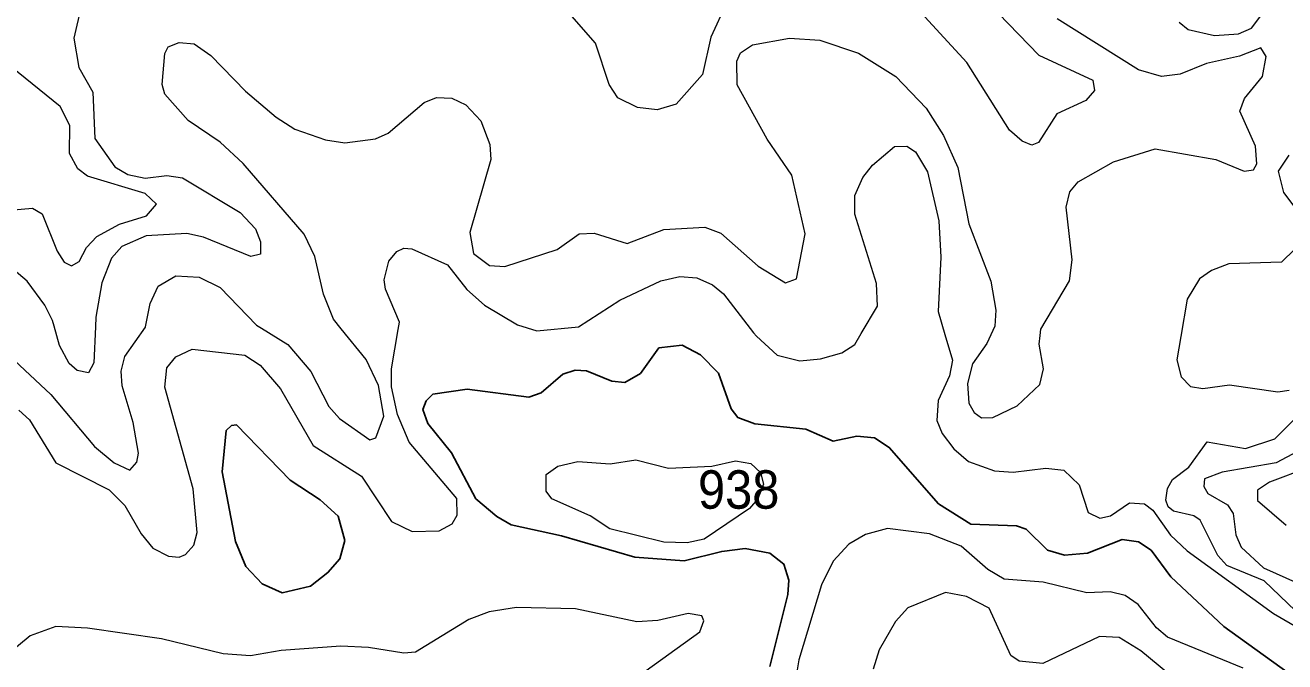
# Model space of a CAD drawing. Extents: x 473.9 to 500, y 7733.1 to 7760.8.
# Drawn here: x 484.875 to 487.498, y 7757.279 to 7758.604 of the extents above; entities that cross this region are included whole.
import ezdxf

# ---------------------------------------------------------------- set-up
doc = ezdxf.new("R2010")
doc.units = 0
doc.header["$LTSCALE"] = 0.032
doc.layers.add('1', color=7, linetype='Continuous', lineweight=25)
doc.layers.add('2', color=7, linetype='Continuous', lineweight=13)
doc.layers.add('21', color=7, linetype='Continuous')

msp = doc.modelspace()

# ---------------------------------------------------------------- linework, layer by layer
at = {"layer": '1'}
for points in [[(486.0435, 7757.8843), (486.0967, 7757.8628), (486.1233, 7757.8604), (486.1561, 7757.8791), (486.1947, 7757.9324), (486.2429, 7757.9381), (486.281, 7757.9181), (486.3185, 7757.8799), (486.3448, 7757.8054), (486.3589, 7757.7872), (486.3945, 7757.7739), (486.5005, 7757.7633), (486.5577, 7757.7384), (486.607, 7757.7485), (486.6436, 7757.7453), (486.6745, 7757.7251), (486.7769, 7757.6077), (486.8447, 7757.565), (486.9396, 7757.5622), (486.9595, 7757.5546), (487.0042, 7757.5114), (487.0392, 7757.5011), (487.0877, 7757.5051), (487.1598, 7757.5335), (487.1933, 7757.5289), (487.22, 7757.5109), (487.2612, 7757.4555), (487.3716, 7757.3522), (487.5572, 7757.2184)], [(486.4257, 7757.269), (486.4634, 7757.4186), (486.4652, 7757.4491), (486.4549, 7757.4823), (486.426, 7757.5052), (486.3745, 7757.5144), (486.3254, 7757.5086), (486.2471, 7757.4888), (486.1444, 7757.4963), (485.992, 7757.5411), (485.8872, 7757.5637), (485.8569, 7757.5812), (485.8136, 7757.6184), (485.7625, 7757.7136), (485.713, 7757.7747), (485.7027, 7757.8037), (485.71, 7757.8223), (485.724, 7757.8357), (485.7955, 7757.8466), (485.9239, 7757.8298), (485.9496, 7757.8387), (485.9948, 7757.8777), (486.0204, 7757.8859), (486.0435, 7757.8843)]]:
    msp.add_lwpolyline(points, dxfattribs=at)
msp.add_lwpolyline([(485.4893, 7757.6158), (485.4266, 7757.657), (485.3147, 7757.7719), (485.3044, 7757.771), (485.2935, 7757.76), (485.2846, 7757.674), (485.3128, 7757.5292), (485.334, 7757.4774), (485.3681, 7757.4408), (485.4095, 7757.4226), (485.4688, 7757.4365), (485.5051, 7757.4644), (485.53, 7757.4932), (485.5402, 7757.5314), (485.5266, 7757.5818)], close=True, dxfattribs=at)
at = {"layer": '2'}
for points in [[(487.2783, 7758.6104), (487.2968, 7758.595), (487.3521, 7758.5827), (487.4018, 7758.586), (487.4292, 7758.5981), (487.4871, 7758.6753)], [(486.3356, 7758.6496), (486.3029, 7758.5793), (486.2855, 7758.5012), (486.2308, 7758.4399), (486.1909, 7758.428), (486.1497, 7758.4328), (486.1091, 7758.4529), (486.0912, 7758.4802), (486.0622, 7758.5665), (485.9987, 7758.6397)], [(486.9018, 7758.6285), (486.9859, 7758.5414), (487.0987, 7758.4896), (487.1019, 7758.4683), (487.0839, 7758.4474), (487.0232, 7758.4195), (486.9856, 7758.3598), (486.9711, 7758.3541), (486.9511, 7758.3626), (486.9249, 7758.3853), (486.8363, 7758.5261), (486.7166, 7758.6562)], [(484.9914, 7758.6432), (484.9758, 7758.5773), (484.9861, 7758.5162), (485.0157, 7758.4647), (485.0193, 7758.3678), (485.0612, 7758.3089), (485.0882, 7758.2934), (485.1242, 7758.2858), (485.1698, 7758.2913), (485.2019, 7758.2865), (485.3227, 7758.2144), (485.354, 7758.18), (485.3647, 7758.1527), (485.3647, 7758.1273), (485.3444, 7758.1224), (485.2461, 7758.1628), (485.2116, 7758.1706), (485.1264, 7758.1656), (485.0758, 7758.1432), (485.0546, 7758.1192), (485.0344, 7758.068), (485.0217, 7757.9962), (485.0208, 7757.9764), (485.0176, 7757.9013), (485.0062, 7757.8806), (484.9825, 7757.885), (484.9662, 7757.8997), (484.9458, 7757.9374), (484.935, 7757.9772), (484.9317, 7757.9892), (484.9157, 7758.0215), (484.8785, 7758.071), (484.8383, 7758.1053)], [(486.1285, 7758.1499), (486.2048, 7758.1785), (486.2906, 7758.1835), (486.3238, 7758.171), (486.4017, 7758.1027), (486.4585, 7758.0679), (486.4811, 7758.0762), (486.4994, 7758.1698), (486.4712, 7758.2917), (486.4204, 7758.3665), (486.3579, 7758.48), (486.357, 7758.5293), (486.3647, 7758.5464), (486.3896, 7758.563), (486.4664, 7758.5767), (486.5298, 7758.5729), (486.6103, 7758.5456), (486.6879, 7758.4975), (486.7514, 7758.4315), (486.7872, 7758.3742), (486.8174, 7758.3075), (486.8405, 7758.1903), (486.8859, 7758.071), (486.8965, 7758.0106), (486.8941, 7757.9772), (486.8859, 7757.9594), (486.8777, 7757.9416), (486.8478, 7757.8994), (486.8376, 7757.8581), (486.8399, 7757.8175), (486.8513, 7757.7975), (486.8664, 7757.7865), (486.8901, 7757.7876), (486.9408, 7757.8115), (486.9882, 7757.8563), (486.996, 7757.8884), (486.9867, 7757.9399), (486.9887, 7757.9584), (486.99, 7757.9709), (487.0502, 7758.0722), (487.0557, 7758.1156), (487.043, 7758.2251), (487.0504, 7758.2572), (487.0683, 7758.278), (487.1415, 7758.3199), (487.2286, 7758.3467), (487.3547, 7758.3245), (487.4135, 7758.3002), (487.4331, 7758.3029), (487.4401, 7758.3151), (487.4371, 7758.3522), (487.4047, 7758.4248), (487.4144, 7758.4515), (487.4516, 7758.4973), (487.4595, 7758.539), (487.4487, 7758.5568), (487.4041, 7758.5393), (487.3352, 7758.5245), (487.2803, 7758.5017), (487.2413, 7758.4975), (487.1937, 7758.5114), (487.0242, 7758.6169)], [(484.7865, 7757.9669), (484.928, 7757.835), (485.0191, 7757.7269), (485.0599, 7757.6931), (485.0923, 7757.6778), (485.1071, 7757.6946), (485.1108, 7757.7131), (485.0997, 7757.777), (485.0763, 7757.853), (485.0743, 7757.8838), (485.0821, 7757.9141), (485.1253, 7757.9755), (485.1255, 7757.9758), (485.1351, 7758.0249), (485.1515, 7758.0606), (485.188, 7758.0822), (485.2368, 7758.0796), (485.2806, 7758.0582), (485.3565, 7757.9797), (485.3668, 7757.9733), (485.4219, 7757.939), (485.4696, 7757.8831), (485.507, 7757.8101), (485.529, 7757.7855), (485.5927, 7757.741), (485.605, 7757.7452), (485.6213, 7757.7903), (485.6103, 7757.8542), (485.5848, 7757.9081), (485.5329, 7757.9718), (485.5165, 7757.9918), (485.4957, 7758.0439), (485.4777, 7758.1227), (485.4557, 7758.1689), (485.3283, 7758.3159), (485.2805, 7758.3604), (485.2138, 7758.4055), (485.1651, 7758.4604), (485.1601, 7758.4804), (485.1657, 7758.5451), (485.1722, 7758.5592), (485.1952, 7758.5678), (485.2267, 7758.5651), (485.2611, 7758.5412), (485.3332, 7758.4669), (485.3971, 7758.4126), (485.4363, 7758.3875), (485.4999, 7758.3656), (485.5402, 7758.3588), (485.6046, 7758.3675), (485.6307, 7758.3793), (485.7058, 7758.4429), (485.731, 7758.4535), (485.7632, 7758.4521), (485.7926, 7758.4384), (485.8236, 7758.4051), (485.8426, 7758.3559), (485.8443, 7758.3244), (485.8008, 7758.1726), (485.8082, 7758.129), (485.8414, 7758.1037), (485.8736, 7758.1014), (485.983, 7758.1372), (486.0285, 7758.1698), (486.06, 7758.1714), (486.1285, 7758.1499)], [(484.8348, 7758.2182), (484.8901, 7758.2229), (484.91, 7758.2114), (484.9411, 7758.1335), (484.956, 7758.1107), (484.9713, 7758.1033), (484.9868, 7758.1118), (485.0023, 7758.1412), (485.0238, 7758.1642), (485.0707, 7758.19), (485.1275, 7758.2071), (485.1484, 7758.2316), (485.1248, 7758.2537), (485.0042, 7758.2894), (484.9842, 7758.3053), (484.967, 7758.3371), (484.9672, 7758.3949), (484.9471, 7758.4347), (484.8154, 7758.5409)], [(486.6497, 7758.0193), (486.6482, 7758.0664), (486.6026, 7758.2106), (486.6025, 7758.2492), (486.6193, 7758.2869), (486.6398, 7758.3127), (486.6852, 7758.3517), (486.7108, 7758.3522), (486.7293, 7758.3403), (486.754, 7758.299), (486.7776, 7758.1967), (486.7817, 7758.1211), (486.7763, 7758.0079), (486.7905, 7757.9603), (486.8065, 7757.9064), (486.8001, 7757.8741), (486.7764, 7757.8225), (486.7736, 7757.7813), (486.7847, 7757.754), (486.809, 7757.7219), (486.8396, 7757.6961), (486.8934, 7757.6764), (486.9328, 7757.6738), (487.0003, 7757.6819), (487.0382, 7757.6776), (487.0702, 7757.6472), (487.0889, 7757.5897), (487.113, 7757.5778), (487.1355, 7757.5826), (487.1748, 7757.6097), (487.2061, 7757.6077), (487.2238, 7757.5942), (487.2606, 7757.5423), (487.2952, 7757.5098), (487.4747, 7757.3797), (487.5314, 7757.3469)], [(487.5069, 7758.3337), (487.4846, 7758.3), (487.4954, 7758.2557), (487.5452, 7758.1908)], [(487.5462, 7758.1641), (487.4918, 7758.1107), (487.3816, 7758.1071), (487.346, 7758.0935), (487.3208, 7758.0761), (487.2951, 7758.0338), (487.2819, 7757.9558), (487.2737, 7757.9072), (487.2828, 7757.8719), (487.3021, 7757.8517), (487.3278, 7757.8475), (487.383, 7757.8554), (487.4838, 7757.841), (487.5072, 7757.8446)], [(484.8614, 7757.8025), (484.8833, 7757.7823), (484.9384, 7757.6928), (485.0492, 7757.6368), (485.0818, 7757.6045), (485.1159, 7757.5453), (485.1407, 7757.5154), (485.173, 7757.4988), (485.1956, 7757.4967), (485.2085, 7757.5021), (485.2255, 7757.5214), (485.2331, 7757.5481), (485.2247, 7757.6386), (485.1656, 7757.8504), (485.1693, 7757.8906), (485.1883, 7757.914), (485.2227, 7757.9296), (485.3318, 7757.9169), (485.3637, 7757.8961), (485.4064, 7757.8471), (485.4747, 7757.729), (485.575, 7757.6656), (485.6378, 7757.5707), (485.6807, 7757.5499), (485.7369, 7757.5518), (485.7642, 7757.5663), (485.7746, 7757.5843), (485.7739, 7757.6188), (485.6742, 7757.7363), (485.6504, 7757.7937), (485.6373, 7757.8509), (485.6373, 7757.889), (485.6516, 7757.9707), (485.6543, 7757.986), (485.6248, 7758.0545), (485.6223, 7758.0738), (485.6322, 7758.1125), (485.6487, 7758.1332), (485.6635, 7758.14), (485.6798, 7758.1387), (485.7539, 7758.1053), (485.7943, 7758.0541), (485.8316, 7758.0215), (485.9002, 7757.9802), (485.9406, 7757.9681), (486.0272, 7757.9759), (486.1131, 7758.0314), (486.1986, 7758.0721), (486.2381, 7758.0806), (486.2733, 7758.0783), (486.3063, 7758.0636), (486.3293, 7758.0448), (486.3918, 7757.9639), (486.3976, 7757.9564), (486.4411, 7757.917), (486.4879, 7757.9054), (486.5314, 7757.9092), (486.5756, 7757.9223), (486.6027, 7757.9396), (486.6158, 7757.9619), (486.6497, 7758.0193)], [(487.521, 7757.3852), (487.4551, 7757.4477), (487.3776, 7757.4793), (487.3592, 7757.5003), (487.3219, 7757.5734), (487.3092, 7757.5827), (487.2664, 7757.5926), (487.2553, 7757.6012), (487.2505, 7757.6151), (487.254, 7757.6398), (487.2646, 7757.6586), (487.2985, 7757.6843), (487.3366, 7757.7369), (487.4163, 7757.7229), (487.4773, 7757.7428), (487.5687, 7757.8347)], [(487.6238, 7757.7691), (487.4801, 7757.6927), (487.368, 7757.6736), (487.3309, 7757.6598), (487.3294, 7757.6437), (487.3383, 7757.6293), (487.3787, 7757.6054), (487.3909, 7757.5877), (487.3967, 7757.5428), (487.4073, 7757.5172), (487.4537, 7757.4744), (487.5272, 7757.442)], [(487.5475, 7757.6836), (487.4667, 7757.6528), (487.4417, 7757.6364), (487.4413, 7757.6143), (487.5011, 7757.5634)], [(487.4119, 7757.2653), (487.2542, 7757.3302), (487.2312, 7757.3497), (487.1928, 7757.3984), (487.1662, 7757.4172), (487.1343, 7757.4245), (487.0861, 7757.4222), (486.9951, 7757.4447), (486.9135, 7757.4511), (486.8801, 7757.4711), (486.8242, 7757.5194), (486.7581, 7757.545), (486.6706, 7757.5564), (486.6253, 7757.544), (486.5903, 7757.5234), (486.5573, 7757.488), (486.5332, 7757.4393), (486.486, 7757.2832), (486.4794, 7757.2416)], [(487.255, 7757.2554), (487.1988, 7757.302), (487.1535, 7757.3293), (487.1123, 7757.3318), (486.9944, 7757.2752), (486.9448, 7757.2801), (486.9277, 7757.2922), (486.8826, 7757.3908), (486.8351, 7757.4146), (486.7914, 7757.4229), (486.7132, 7757.3915), (486.6877, 7757.3625), (486.6533, 7757.3037), (486.6408, 7757.2635)], [(486.1509, 7757.2481), (486.28, 7757.341), (486.2883, 7757.3641), (486.2838, 7757.3745), (486.2558, 7757.3795), (486.1927, 7757.3649), (486.1485, 7757.3619), (486.021, 7757.3891), (485.8978, 7757.3916), (485.8413, 7757.3828), (485.7986, 7757.3671), (485.6876, 7757.2991), (485.663, 7757.2968), (485.59, 7757.3089), (485.532, 7757.3112), (485.4078, 7757.3022), (485.344, 7757.291), (485.2866, 7757.2951), (485.1582, 7757.3266), (485.0046, 7757.3489), (484.9383, 7757.3521), (484.885, 7757.3328), (484.8362, 7757.2924)]]:
    msp.add_lwpolyline(points, dxfattribs=at)
msp.add_lwpolyline([(486.2052, 7757.5278), (486.0921, 7757.5553), (486.0517, 7757.5824), (485.9715, 7757.6179), (485.9595, 7757.6339), (485.9601, 7757.6685), (485.9841, 7757.6859), (486.0258, 7757.6955), (486.0928, 7757.6907), (486.1463, 7757.6995), (486.2145, 7757.6819), (486.3052, 7757.6859), (486.3544, 7757.6971), (486.3863, 7757.6914), (486.406, 7757.6727), (486.4126, 7757.6485), (486.4005, 7757.6184), (486.3835, 7757.5978), (486.289, 7757.5339), (486.2536, 7757.5267)], close=True, dxfattribs=at)

# ---------------------------------------------------------------- texts
at = {"layer": '21', "width": 0.95}
msp.add_text('938', height=0.08, dxfattribs=at).set_placement((486.276, 7757.5975))

doc.saveas('drawing.dxf')
